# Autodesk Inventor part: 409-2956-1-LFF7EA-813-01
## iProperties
Created: 2010-11
Part Number: 409-2956-1-LFF7EA-813-01
Material: 3/8" OD TUBE - SS
Description: PT TUBING
Document SubType Name: Modeling
Designer: S. Boerckel
Engineer: Steve Boerckel
Mass: 769.029 g
Surface Area: 1665.99 cm^2
Volume: 95.1769 cm^3
Density: 8.08 g/cm^3
Length: 140.650 in
Author: S. Boerckel
Revision Number: 0
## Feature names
1. Sweep1
